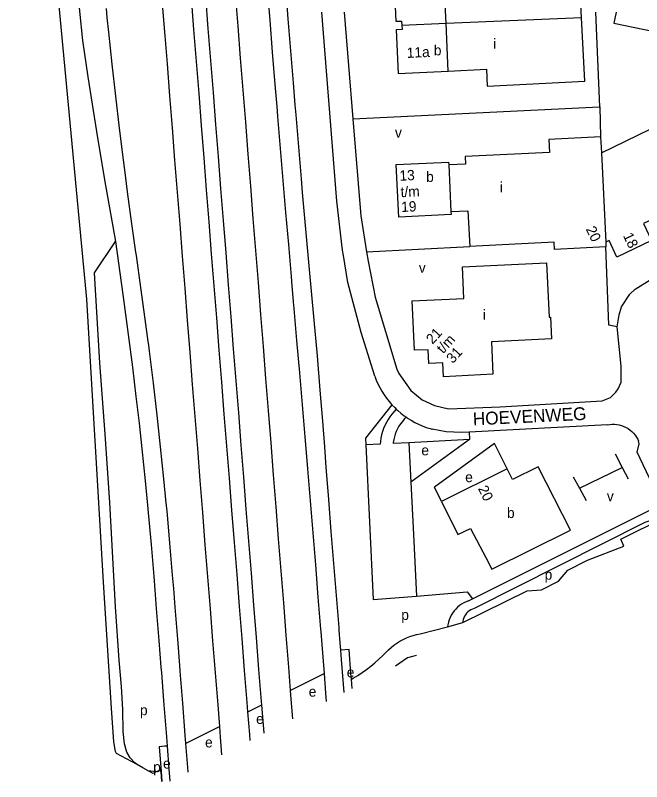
# Model space of a CAD drawing. Extents: x 157699 to 159683, y 381451 to 383293.
# Drawn here: x 157774.5 to 158018.2, y 381450.8 to 381748.7 of the extents above; entities that cross this region are included whole.
import ezdxf

# ---------------------------------------------------------------- set-up
doc = ezdxf.new("R2010")
doc.units = 0
for name, color, linetype in [('BLT_Basislijn', 7, 'Continuous'), ('BLT_Bebouwing', 7, 'Continuous'), ('BLT_Centroide', 7, 'Continuous'), ('BLT_Gemeentegrens', 7, 'Continuous'), ('BLT_Huisnummer', 7, 'Continuous'), ('BLT_Huisnummer_reeks', 7, 'Continuous'), ('BLT_Onderverdeling_panden', 7, 'Continuous'), ('BLT_Straatnaam', 7, 'Continuous'), ('BLT_Vlakafsluiter', 7, 'Continuous')]:
    doc.layers.add(name, color=color, linetype=linetype)

msp = doc.modelspace()

# ---------------------------------------------------------------- linework, layer by layer
at = {"layer": 'BLT_Basislijn'}
for p, q in [((157902.49, 381750), (157905.84, 381708.55)), ((158000.2, 381750), (158001.76, 381713.17)), ((157905.84, 381708.55), (158001.76, 381713.17)), ((158001.76, 381713.17), (158001.88, 381713.17)), ((158001.88, 381713.17), (158002.11, 381701.5)), ((157911.12, 381656.82), (157951.29, 381658.85)), ((157911.12, 381656.82), (157911.71, 381653.09)), ((157951.08, 381586.74), (157951.17, 381583.79)), ((157916.43, 381582.03), (157910.88, 381581.75)), ((157927.54, 381582.59), (157921.47, 381582.29)), ((157951.17, 381583.79), (157927.54, 381582.59)), ((157927.54, 381582.59), (157928.31, 381567.27)), ((157951.17, 381583.79), (157928.31, 381567.27)), ((157960.96, 381582.23), (157937.51, 381565.27)), ((157965.86, 381572.37), (157960.96, 381582.23)), ((158007.79, 381578.24), (158010.54, 381573)), ((157994, 381564.85), (158010.54, 381573)), ((158010.54, 381573), (158012.88, 381568.57)), ((157928.31, 381567.27), (157929.34, 381546.95)), ((157991.51, 381569.33), (157994, 381564.85)), ((157940.3, 381559.67), (157937.51, 381565.27)), ((157994, 381564.85), (157996.59, 381560.17)), ((157952.35, 381521.92), (158028.36, 381559.84)), ((157929.34, 381546.95), (157930.54, 381522.98)), ((157950.76, 381521.12), (157952.35, 381521.92)), ((157931.99, 381508.28), (157942.61, 381510.99)), ((157942.61, 381510.99), (157948.53, 381512.72)), ((157881.47, 381486.26), (157894.59, 381492.88)), ((157864.98, 381477.92), (157870.38, 381480.65)), ((157840.77, 381465.69), (157853.88, 381472.31))]:
    msp.add_line(p, q, dxfattribs=at)
for points in [[(157777.17, 381985.59), (157779.91, 381967.9), (157782.03, 381953.71), (157783.5, 381941.99), (157784.77, 381930.34), (157786.03, 381916.92), (157786.85, 381906.41), (157787.93, 381893.2), (157788.96, 381879.81), (157790.06, 381866.4), (157792.11, 381840.1), (157794.2, 381813.47), (157795.32, 381799.46), (157797.34, 381773.96), (157799.47, 381750.35), (157800.68, 381738.99), (157802.74, 381724.81), (157806.1, 381703.5), (157809.24, 381684.74), (157813.48, 381660.81)], [(157886.27, 381679.89), (157885.83, 381685.13), (157884.78, 381697.58), (157883.75, 381710.03), (157883.43, 381713.91), (157882.72, 381722.48), (157881.71, 381734.94), (157880.7, 381747.39), (157879.7, 381759.85), (157878.81, 381771.05), (157878.71, 381772.3), (157877.94, 381782.04), (157877.73, 381784.76), (157876.74, 381797.22), (157876.25, 381803.45)], [(157872.47, 381759.27), (157873.47, 381746.81), (157874.48, 381734.35), (157875.5, 381721.89), (157876.2, 381713.31), (157876.52, 381709.43), (157877.56, 381696.98), (157878.6, 381684.52), (157879.65, 381672.06), (157880.72, 381659.61), (157881.79, 381647.15), (157881.96, 381645.19), (157882.64, 381637.33), (157882.87, 381634.7), (157883.95, 381622.25), (157885.01, 381609.79), (157886.07, 381597.34), (157887.12, 381584.88), (157887.77, 381577.16), (157888.16, 381572.43), (157889.19, 381559.97), (157890.21, 381547.51), (157891.23, 381535.05), (157892.23, 381522.59), (157893.22, 381510.13), (157893.31, 381509.11), (157893.69, 381504.19), (157894.21, 381497.67), (157894.59, 381492.88)], [(157831.55, 381754.78), (157832.53, 381742.31), (157833.52, 381729.85), (157834.5, 381717.39), (157835.49, 381704.93), (157836.47, 381692.47), (157837.46, 381680.01), (157838.45, 381667.55), (157839.43, 381655.09), (157840.42, 381642.63), (157841.4, 381630.16), (157842.39, 381617.7), (157843.37, 381605.24), (157844.36, 381592.78), (157845.34, 381580.32), (157846.33, 381567.86), (157847.31, 381555.4), (157848.3, 381542.94), (157849.28, 381530.48), (157850.27, 381518.02), (157851.26, 381505.55), (157852.24, 381493.09), (157853.23, 381480.63), (157853.88, 381472.31)], [(157864.98, 381477.92), (157864.69, 381481.54), (157863.7, 381494), (157862.72, 381506.46), (157861.73, 381518.92), (157860.75, 381531.38), (157859.76, 381543.84), (157858.78, 381556.3), (157857.79, 381568.77), (157856.81, 381581.23), (157855.82, 381593.69), (157854.84, 381606.15), (157853.85, 381618.61), (157852.87, 381631.07), (157851.88, 381643.53), (157850.89, 381655.99), (157849.91, 381668.45), (157848.92, 381680.92), (157847.94, 381693.38), (157846.95, 381705.84), (157845.97, 381718.3), (157844.98, 381730.76), (157844, 381743.22), (157843.01, 381755.68)], [(157870.38, 381480.65), (157870.27, 381481.98), (157869.29, 381494.44), (157868.3, 381506.9), (157867.32, 381519.36), (157866.33, 381531.82), (157865.35, 381544.29), (157864.36, 381556.75), (157863.38, 381569.21), (157862.39, 381581.67), (157861.4, 381594.13), (157860.42, 381606.59), (157859.43, 381619.05), (157858.45, 381631.51), (157857.46, 381643.97), (157856.48, 381656.44), (157855.49, 381668.9), (157854.51, 381681.36), (157853.52, 381693.82), (157852.54, 381706.28), (157851.55, 381718.74), (157850.57, 381731.2), (157849.58, 381743.66), (157848.59, 381756.12)], [(157860.06, 381757.03), (157861.04, 381744.57), (157862.03, 381732.11), (157863.02, 381719.65), (157864, 381707.19), (157864.99, 381694.72), (157865.97, 381682.26), (157866.96, 381669.8), (157867.94, 381657.34), (157868.93, 381644.88), (157869.91, 381632.42), (157870.9, 381619.96), (157871.88, 381607.5), (157872.87, 381595.04), (157873.85, 381582.58), (157874.84, 381570.11), (157875.82, 381557.65), (157876.81, 381545.19), (157877.8, 381532.73), (157878.78, 381520.27), (157879.77, 381507.81), (157880.75, 381495.35), (157881.47, 381486.26)], [(157809.83, 381751.35), (157810.17, 381747.87), (157810.74, 381742.16), (157812.05, 381729.73), (157813.43, 381717.31), (157814.9, 381704.9), (157816.44, 381692.5), (157817.2, 381686.57), (157818.05, 381680.1), (157819.75, 381667.72), (157821.32, 381656.7), (157821.52, 381655.35), (157823.27, 381642.97), (157824.95, 381630.58), (157826.07, 381621.96), (157826.27, 381620.44)], [(157899.14, 381681.43), (157893.74, 381750)], [(157905.84, 381708.55), (157908.88, 381670.8), (157911.12, 381656.82)], [(157902.19, 381655.3), (157901.83, 381657.45), (157899.53, 381676.49), (157899.14, 381681.43)], [(157888.79, 381651.35), (157886.27, 381679.89)], [(157813.48, 381660.81), (157816.38, 381640.19), (157818.46, 381624.59), (157820.07, 381611.93), (157821.45, 381600.58), (157822.7, 381590.15), (157823.68, 381580.15), (157824.97, 381567.76), (157825.89, 381558.35), (157826.17, 381555.37), (157827.3, 381542.96), (157828.36, 381530.55), (157828.77, 381525.39), (157829.35, 381518.1), (157830.33, 381505.64), (157831.14, 381495.38), (157831.32, 381493.18), (157832.17, 381482.41)], [(158008.63, 381627.66), (158009.36, 381632.35), (158010.31, 381635.34), (158013.56, 381640.27), (158015.56, 381642.29), (158021.48, 381645.93), (158038.06, 381653.74), (158050, 381659.32)], [(158008.63, 381627.66), (158005.39, 381628.22), (158004.21, 381658.68)], [(157914.35, 381608.43), (157908.99, 381625.43), (157903.91, 381644.81), (157902.19, 381655.3)], [(157894.95, 381580.98), (157894.14, 381590.91), (157893.09, 381602.99), (157892, 381616.38), (157890.76, 381630.28), (157888.79, 381651.35)], [(157911.71, 381653.09), (157914.54, 381639.22), (157922.97, 381611.22), (157923.76, 381609.47), (157928.38, 381602.87), (157932.77, 381599.22), (157937.51, 381596.99), (157943.01, 381595.71), (157963.14, 381596.47), (158002.84, 381598.89), (158006.06, 381600.14), (158008.11, 381602.17), (158009.05, 381603.51), (158010.15, 381606.13), (158010.12, 381612.38), (158008.63, 381627.66)], [(157821.62, 381457.57), (157821.04, 381458.08), (157819.16, 381460.02), (157817.92, 381462.28), (157816.95, 381465.46), (157816.41, 381470.36), (157816.32, 381478.89), (157815.83, 381487.77), (157814.97, 381498.06), (157813.51, 381518.76), (157811.32, 381559.37), (157809.5, 381585.92), (157807.36, 381613.62), (157805.38, 381648.56)], [(157826.27, 381620.44), (157826.55, 381618.18), (157828.08, 381605.77), (157829.52, 381593.35), (157830.89, 381580.93), (157832.18, 381568.49), (157833.11, 381559.04), (157833.39, 381556.05), (157834.53, 381543.59), (157835.58, 381531.14), (157836, 381525.96), (157836.58, 381518.67), (157837.56, 381506.21), (157838.37, 381495.96), (157838.55, 381493.75), (157839.53, 381481.29), (157840.52, 381468.83), (157840.77, 381465.69)], [(157914.35, 381608.43), (157914.93, 381606.92), (157915.59, 381605.44), (157916.32, 381603.99), (157917.12, 381602.58), (157917.99, 381601.22), (157918.92, 381599.89), (157919.92, 381598.62), (157921.02, 381597.35)], [(157921.02, 381597.35), (157910.76, 381584.36), (157910.88, 381581.75)], [(157921.02, 381597.35), (157922.1, 381596.23), (157922.72, 381595.64)], [(157922.72, 381595.64), (157921.82, 381594.7), (157920.98, 381593.71), (157920.2, 381592.68), (157919.49, 381591.6), (157918.85, 381590.48), (157918.27, 381589.32), (157917.77, 381588.12), (157917.35, 381586.9), (157917, 381585.65), (157916.73, 381584.39), (157916.54, 381583.11), (157916.43, 381582.03)], [(157922.72, 381595.64), (157923.28, 381595.11), (157924.51, 381594.06), (157925.79, 381593.07), (157926.65, 381592.46)], [(157926.65, 381592.46), (157925.83, 381591.67), (157925.08, 381590.83), (157924.39, 381589.94), (157923.76, 381589), (157923.2, 381588.02), (157922.72, 381587), (157922.3, 381585.95), (157921.96, 381584.87), (157921.7, 381583.78), (157921.52, 381582.66), (157921.47, 381582.29)], [(157926.65, 381592.46), (157927.11, 381592.14), (157928.49, 381591.28), (157929.9, 381590.49), (157931.35, 381589.77), (157932.83, 381589.12), (157934.35, 381588.54), (157935.89, 381588.04), (157936.68, 381587.82)], [(157951.08, 381586.74), (157948.04, 381586.58), (157942.11, 381586.83), (157936.68, 381587.82)], [(158004.83, 381589.55), (157951.08, 381586.74)], [(158004.83, 381589.55), (158005.75, 381589.7), (158006.68, 381589.76), (158007.61, 381589.75), (158008.54, 381589.66), (158009.46, 381589.49), (158010.36, 381589.24), (158011.23, 381588.91), (158012.08, 381588.51), (158012.88, 381588.04), (158013.65, 381587.51), (158014.36, 381586.91), (158015.02, 381586.25), (158015.62, 381585.53), (158016.16, 381584.77), (158016.63, 381583.96), (158016.92, 381583.37)], [(157910.88, 381581.75), (157913.72, 381521.61), (157930.54, 381522.98)], [(158028.36, 381559.84), (158025.47, 381565.25), (158022.36, 381566.33), (158016.43, 381578.93), (158017.17, 381582.14), (158016.92, 381583.37)], [(157901.15, 381501.89), (157900.92, 381504.76), (157900.53, 381509.68), (157900.45, 381510.71), (157899.46, 381523.17), (157898.45, 381535.64), (157897.44, 381548.1), (157896.42, 381560.56), (157895.39, 381573.03), (157894.95, 381580.98)], [(158026.95, 381554.17), (158019.39, 381551.51), (157952.98, 381518.16)], [(158011.15, 381542.3), (158009.99, 381545.03), (158027.25, 381553.57), (158026.95, 381554.17)], [(157948.53, 381512.72), (157973.57, 381525.05), (157979.15, 381525.32), (157985.82, 381528.78), (157989.4, 381533.06), (157997.1, 381536.94), (158011.15, 381542.3)], [(157930.54, 381522.98), (157950.26, 381524.58), (157952.35, 381521.92)], [(157950.76, 381521.12), (157949.83, 381520.76), (157948.94, 381520.32), (157948.09, 381519.81), (157947.29, 381519.24), (157946.53, 381518.6), (157945.82, 381517.91), (157945.18, 381517.16), (157944.59, 381516.35), (157944.08, 381515.51), (157943.63, 381514.62), (157943.25, 381513.71), (157942.95, 381512.76), (157942.73, 381511.8), (157942.61, 381510.99)], [(157952.98, 381518.16), (157952.31, 381517.92), (157951.68, 381517.61), (157951.09, 381517.23), (157950.54, 381516.78), (157950.04, 381516.28), (157949.61, 381515.72), (157949.24, 381515.11), (157948.95, 381514.47), (157948.72, 381513.8), (157948.58, 381513.11), (157948.53, 381512.72)], [(157919.65, 381502.1), (157920.7, 381503.02), (157921.8, 381503.89), (157922.95, 381504.68), (157924.14, 381505.42), (157925.37, 381506.08), (157926.64, 381506.67), (157927.94, 381507.18), (157929.27, 381507.62), (157930.62, 381507.99), (157931.99, 381508.28)], [(157905.08, 381492.81), (157904.35, 381502.14), (157901.15, 381501.89)], [(157902.44, 381485.52), (157901.44, 381498.24), (157901.15, 381501.89)], [(157905.24, 381490.7), (157905.9, 381491.06), (157907.7, 381492.11), (157909.45, 381493.24), (157911.15, 381494.43), (157912.81, 381495.68), (157914.42, 381497), (157915.97, 381498.38), (157917.47, 381499.81), (157918.92, 381501.31), (157919.65, 381502.1)], [(157930.6, 381499.88), (157929.52, 381499.63), (157927.05, 381498.89), (157922.42, 381495.71)], [(157894.59, 381492.88), (157895.2, 381485.21), (157895.45, 381481.96)], [(157905.24, 381490.7), (157905.08, 381492.81)], [(157905.52, 381487.09), (157905.24, 381490.7)], [(157881.47, 381486.26), (157881.74, 381482.89), (157882.34, 381475.27)], [(157832.17, 381482.41), (157832.3, 381480.72), (157833.29, 381468.26), (157833.58, 381464.63)], [(157871.25, 381469.61), (157870.38, 381480.65)], [(157865.85, 381466.86), (157865.68, 381469.08), (157864.98, 381477.92)], [(157853.88, 381472.31), (157854.21, 381468.17), (157854.76, 381461.2)], [(157840.77, 381465.69), (157841.5, 381456.37), (157841.65, 381454.52)], [(157832.52, 381464.55), (157830.51, 381464.4), (157831.26, 381454.74)], [(157833.58, 381464.63), (157832.52, 381464.55)], [(157833.58, 381464.63), (157834.27, 381455.8), (157834.66, 381450.95)], [(157829.35, 381454.65), (157827.28, 381454.85), (157826.25, 381455.05)], [(157831.26, 381454.74), (157831.18, 381454.74)], [(157831.19, 381454.7), (157831.26, 381454.74)], [(157831.26, 381454.74), (157831.56, 381450.81)]]:
    msp.add_lwpolyline(points, dxfattribs=at)
at = {"layer": 'BLT_Bebouwing'}
for p, q in [((158002.5, 381695.32), (158021.49, 381704.53)), ((158002.11, 381701.5), (158002.5, 381695.32)), ((157984.07, 381660.5), (157951.29, 381658.85)), ((157965.86, 381572.37), (157940.3, 381559.67)), ((157959.89, 381533.4), (157990.46, 381548.61)), ((157957.53, 381537.9), (157959.89, 381533.4))]:
    msp.add_line(p, q, dxfattribs=at)
for points in [[(157994.79, 381747.81), (157993.51, 381773.49), (157955.6, 381771.62), (157955.93, 381765.08), (157941.1, 381764.32)], [(157941.1, 381764.32), (157921.69, 381763.33), (157922.56, 381746.39), (157924.78, 381746.5), (157924.85, 381744.83)], [(158008.27, 381750), (158007.37, 381745.62), (158050, 381736.86)], [(157942.9, 381727.04), (157957.74, 381727.73), (157958.07, 381721.21), (157996.02, 381723.11), (157994.79, 381747.81)], [(157924.85, 381744.83), (157924.93, 381743.16), (157922.71, 381743.06), (157923.47, 381726.14), (157942.9, 381727.04)], [(158002.11, 381701.5), (157981.99, 381700.49), (157982.25, 381695.45), (157949.56, 381693.8), (157949.69, 381690.91), (157943.12, 381690.58)], [(157943.98, 381672.45), (157944.04, 381671.31), (157923.66, 381670.29), (157922.66, 381690.68), (157943.06, 381691.69), (157943.12, 381690.58)], [(158035.42, 381675.59), (158018.85, 381667.83), (158021.94, 381661.24), (158008.55, 381654.76), (158005.46, 381661.15), (158004.2, 381660.58)], [(157943.98, 381672.45), (157950.58, 381672.77), (157951.29, 381658.85)], [(158004.21, 381658.68), (157984.21, 381657.69), (157984.07, 381660.5)], [(158004.2, 381660.58), (158004.21, 381658.68)], [(157990.46, 381548.61), (157977.93, 381573.25), (157967.89, 381568.29), (157965.86, 381572.37)], [(157940.3, 381559.67), (157946.67, 381546.86), (157951.57, 381549.27), (157957.53, 381537.9)]]:
    msp.add_lwpolyline(points, dxfattribs=at)
msp.add_lwpolyline([(157948.43, 381650.91), (157981.18, 381652.49), (157982.23, 381631.32), (157982.65, 381631.35), (157983.02, 381622.91), (157959.68, 381621.78), (157960.27, 381609.19), (157941.08, 381608.24), (157940.81, 381613.63), (157935.41, 381613.36), (157935.15, 381618.73), (157929.77, 381618.5), (157928.87, 381637.69), (157948.99, 381638.64)], close=True, dxfattribs=at)
at = {"layer": 'BLT_Gemeentegrens'}
for points in [[(157821.62, 381457.57), (157813.89, 381461.78), (157813.54, 381462.57), (157812.82, 381466.24), (157811.88, 381479.42), (157808.82, 381528.32), (157802.33, 381638.43), (157799.33, 381669.9), (157791.09, 381758.11), (157790.95, 381765.11), (157790.89, 381768.47), (157790.24, 381786.83), (157790.21, 381787.45), (157789.89, 381794.11), (157787.02, 381829.01), (157779.86, 381917.92), (157776.96, 381954.82), (157774.91, 381971.23), (157774.54, 381972.47), (157774.93, 381972.56), (157774.52, 381975.12)], [(157826.25, 381455.05), (157824.18, 381456.18), (157821.62, 381457.57)], [(157829.35, 381454.65), (157828.11, 381454.04), (157826.25, 381455.05)], [(157831.18, 381454.74), (157831.12, 381455.52), (157829.91, 381454.93), (157829.35, 381454.65)], [(157831.19, 381454.7), (157831.18, 381454.74)], [(157831.49, 381450.81), (157831.19, 381454.7)]]:
    msp.add_lwpolyline(points, dxfattribs=at)
at = {"layer": 'BLT_Onderverdeling_panden'}
for p, q in [((157942.11, 381745.57), (157941.1, 381764.32)), ((157942.11, 381745.57), (157924.85, 381744.83)), ((157994.79, 381747.81), (157942.11, 381745.57)), ((157942.9, 381727.04), (157942.11, 381745.57)), ((158002.5, 381695.32), (158004.2, 381660.58)), ((157943.12, 381690.58), (157943.98, 381672.45))]:
    msp.add_line(p, q, dxfattribs=at)
at = {"layer": 'BLT_Vlakafsluiter'}
msp.add_line((157805.38, 381648.56), (157813.48, 381660.81), dxfattribs=at)

# ---------------------------------------------------------------- texts
at = {"layer": 'BLT_Centroide'}
for s, p in [('i', (157960.37, 381735.72)), ('b', (157937.31, 381733.16)), ('v', (157922.19, 381701.16)), ('b', (157934.31, 381683.98)), ('i', (157962.97, 381679.94)), ('v', (157931.47, 381648.63)), ('i', (157956.38, 381630.38)), ('e', (157932.45, 381577.66)), ('e', (157949.51, 381567.22)), ('v', (158004.62, 381559.84)), ('b', (157965.76, 381553.31)), ('p', (157980.41, 381529.32)), ('p', (157924.64, 381513.67)), ('e', (157903.44, 381491.34)), ('e', (157888.65, 381483.84)), ('p', (157823, 381476.64)), ('e', (157868.18, 381473.24)), ('e', (157848.33, 381464.12)), ('p', (157828.14, 381454.53)), ('e', (157831.98, 381455.91))]:
    msp.add_text(s, height=4, dxfattribs=at).set_placement(p)
at = {"layer": 'BLT_Huisnummer'}
for s, rotation, p in [('11a', 2.7491, (157926.86, 381732.14)), ('18', 295.7997, (158010.8, 381663.1)), ('20', 296.4665, (157954.38, 381564.75))]:
    msp.add_text(s, height=4, rotation=rotation, dxfattribs=at).set_placement(p)
at = {"layer": 'BLT_Huisnummer_reeks'}
for s, rotation, p in [('13', 2.7531, (157924.02, 381684.4)), ('t/m', 2.7541, (157924.47, 381678.01)), ('19', 2.7541, (157924.7, 381672.25)), ('20', 295.7997, (157996.34, 381665.6)), ('21', 47.628, (157936.82, 381620.62)), ('t/m', 47.628, (157940.92, 381616.95)), ('31', 47.628, (157944.7, 381613.14))]:
    msp.add_text(s, height=4, rotation=rotation, dxfattribs=at).set_placement(p)
at = {"layer": 'BLT_Straatnaam'}
msp.add_text('HOEVENWEG', height=5, rotation=2.8288, dxfattribs=at).set_placement((157952.61, 381589.29))

doc.saveas('drawing.dxf')
